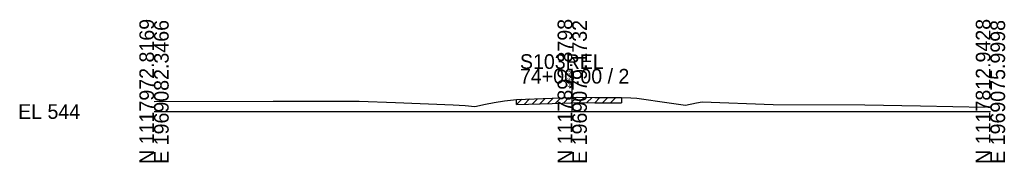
# Model space of a CAD drawing. Extents: x -26 to 163, y -10 to 24518.
# Drawn here: x -25.7 to 162.8, y 22490.3 to 22517.5 of the extents above; entities that cross this region are included whole.
import ezdxf

# ---------------------------------------------------------------- set-up
doc = ezdxf.new("R2010")
doc.units = 0
for name, color, linetype in [('RD_GPK_XS_Cell', 7, 'Continuous'), ('RD_XS_ExGround', 7, 'Continuous'), ('RD_XS_ExPaveRet', 7, 'Continuous'), ('RD_XS_TX_Elev_EX', 7, 'Continuous')]:
    doc.layers.add(name, color=color, linetype=linetype)

msp = doc.modelspace()

# ---------------------------------------------------------------- linework, layer by layer
at = {"layer": 'RD_GPK_XS_Cell'}
for p, q in [((80, 22500), (80, 22508.14)), ((0, 22500), (80, 22500)), ((80, 22500), (160, 22500))]:
    msp.add_line(p, q, dxfattribs=at)
at = {"layer": 'RD_XS_ExGround'}
msp.add_lwpolyline([(0, 22501.92), (22.77, 22501.99), (39.25, 22501.96), (46.19, 22501.7), (57.25, 22501.29), (59.49, 22501.13), (61.36, 22500.95), (63.44, 22501.38), (65.07, 22501.75), (67.04, 22502.02), (69.31, 22502.31), (76.17, 22502.54), (80, 22502.68), (81.05, 22502.71), (84.31, 22502.68), (89.45, 22502.66), (91.24, 22502.6), (92.33, 22502.57), (98.54, 22501.68), (101.68, 22501.23), (103.75, 22501.68), (104.83, 22501.87), (118.43, 22501.32), (135.95, 22501.27), (146.59, 22501.06), (159.02, 22500.83)], dxfattribs=at)
at = {"layer": 'RD_XS_ExPaveRet'}
for p, q in [((69.31, 22501.31), (70.35, 22502.35)), ((69.31, 22501.31), (69.31, 22502.31)), ((69.31, 22501.31), (76.17, 22501.54)), ((70.81, 22501.36), (71.85, 22502.4)), ((72.31, 22501.41), (73.35, 22502.45)), ((73.81, 22501.46), (74.85, 22502.5)), ((75.31, 22501.51), (76.35, 22502.55)), ((76.17, 22501.54), (80, 22501.68)), ((76.81, 22501.57), (77.85, 22502.6)), ((78.31, 22501.62), (79.35, 22502.65)), ((79.81, 22501.67), (80.85, 22502.71)), ((80, 22501.68), (81.05, 22501.71)), ((81.05, 22501.71), (84.31, 22501.68)), ((81.31, 22501.71), (82.3, 22502.7)), ((82.81, 22501.7), (83.8, 22502.69)), ((84.31, 22501.68), (85.31, 22502.68)), ((84.31, 22501.68), (89.45, 22501.66)), ((85.81, 22501.67), (86.81, 22502.67)), ((87.31, 22501.67), (88.31, 22502.66)), ((89.45, 22502.66), (89.45, 22501.66))]:
    msp.add_line(p, q, dxfattribs=at)

# ---------------------------------------------------------------- texts
at = {"layer": 'RD_GPK_XS_Cell'}
for s, p in [('N 1117972.8169', (0, 22490)), ('E 1969082.3466', (2.8, 22490)), ('N 1117892.8798', (80, 22490)), ('E 1969079.1732', (82.8, 22490)), ('N 1117812.9428', (160, 22490)), ('E 1969075.9998', (162.8, 22490))]:
    msp.add_text(s, height=2.8, rotation=90, dxfattribs=at).set_placement(p)
for s, p in [('S103REL', (70, 22508.14)), ('74+00.00 / 2', (70, 22505.34)), ('EL 544', (-26, 22498.6))]:
    msp.add_text(s, height=2.8, dxfattribs=at).set_placement(p)
at = {"layer": 'RD_XS_TX_Elev_EX'}
msp.add_text('546.68', height=0.8, rotation=90, dxfattribs=at).set_placement((79.9, 22504.68))

doc.saveas('drawing.dxf')
